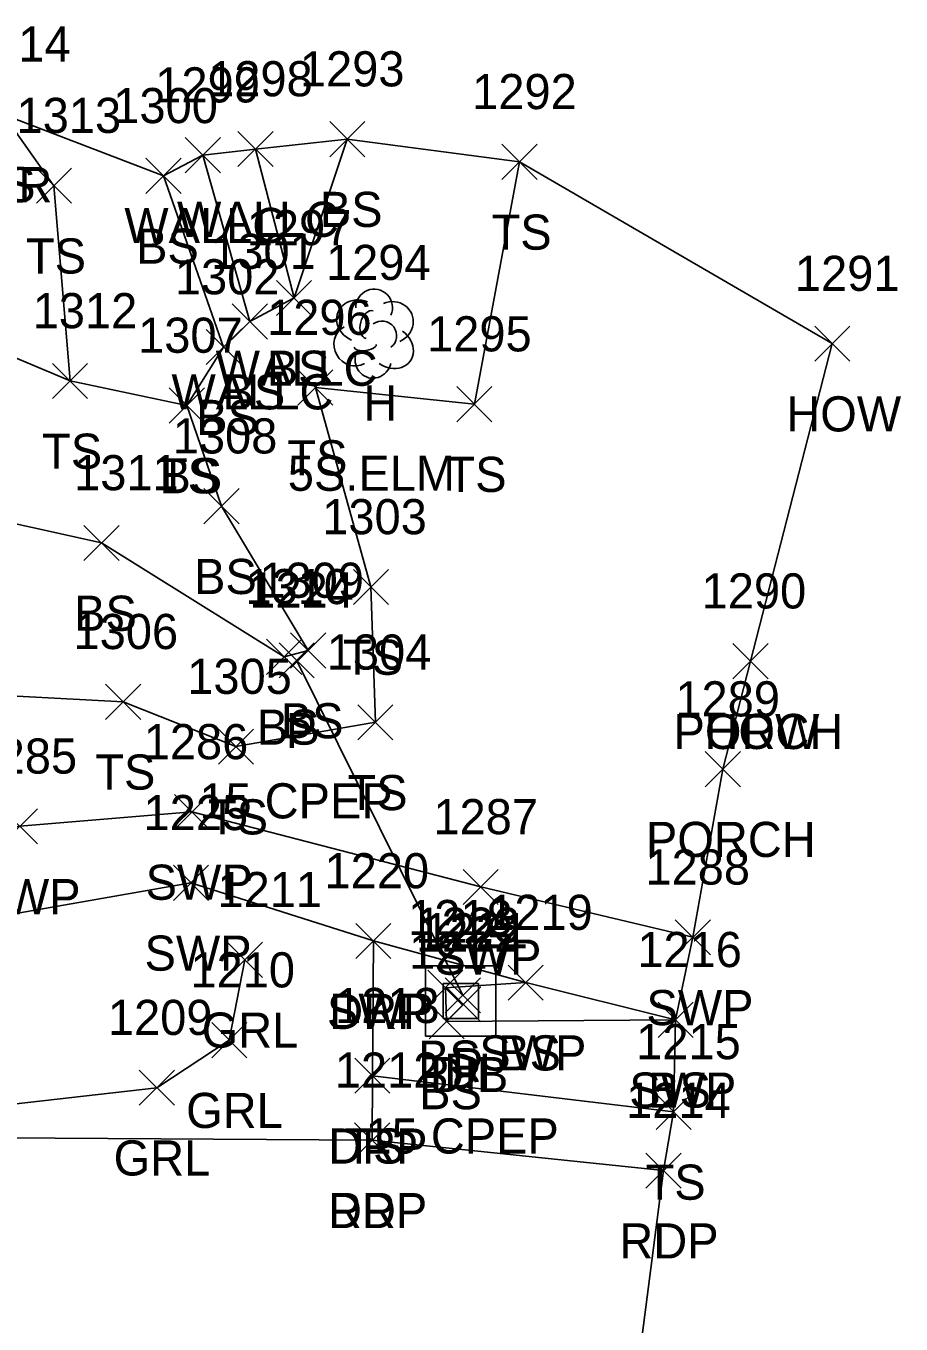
# Model space of a CAD drawing. Extents: x 1505684 to 1510253, y 730355 to 731397.
# Drawn here: x 1510203.3 to 1510253.1, y 730918.5 to 730992.4 of the extents above; entities that cross this region are included whole.
import ezdxf

# ---------------------------------------------------------------- set-up
doc = ezdxf.new("R2010")
doc.units = 0
for name, color, linetype in [('D_A', 7, 'Continuous'), ('D_C', 7, 'Continuous'), ('D_I', 7, 'Continuous'), ('D_TIC', 7, 'Continuous'), ('DCP', 7, 'Continuous'), ('DS', 7, 'Continuous'), ('L_A', 7, 'Continuous'), ('L_C', 7, 'Continuous'), ('L_I', 7, 'Continuous'), ('L_TIC', 7, 'Continuous'), ('LBC', 7, 'Continuous'), ('LBF', 7, 'Continuous'), ('LELB', 7, 'Continuous'), ('LSOGP', 7, 'Continuous'), ('LTD', 7, 'Continuous'), ('LW', 7, 'Continuous'), ('P_A', 7, 'Continuous'), ('P_I', 7, 'Continuous'), ('P_TIC', 7, 'Continuous'), ('PET', 7, 'Continuous'), ('R_A', 7, 'Continuous'), ('R_I', 7, 'Continuous'), ('R_TIC', 7, 'Continuous'), ('RDP', 7, 'Continuous'), ('RGR', 7, 'Continuous'), ('RSW', 7, 'Continuous')]:
    doc.layers.add(name, color=color, linetype=linetype)

msp = doc.modelspace()

# ---------------------------------------------------------------- linework, layer by layer
at = {"layer": 'D_TIC'}
for points in [[(1510217.701, 730955.254), (1510219.701, 730957.254)], [(1510219.701, 730955.254), (1510217.701, 730957.254)], [(1510227.154, 730936.18), (1510229.154, 730938.18)], [(1510229.154, 730936.18), (1510227.154, 730938.18)], [(1510227.185, 730935.675), (1510229.185, 730937.675)], [(1510229.185, 730935.675), (1510227.185, 730937.675)]]:
    msp.add_lwpolyline(points, dxfattribs=at)
at = {"layer": 'DCP'}
msp.add_lwpolyline([(1510228.154, 730937.18), (1510218.701, 730956.254)], dxfattribs=at)
at = {"layer": 'DS'}
for p, q in [((1510226.041, 730938.864), (1510230.041, 730938.864)), ((1510226.041, 730934.864), (1510226.041, 730938.864)), ((1510230.041, 730938.864), (1510230.041, 730934.864)), ((1510227.041, 730935.864), (1510227.041, 730937.864)), ((1510227.041, 730937.864), (1510229.041, 730937.864)), ((1510229.041, 730937.864), (1510229.041, 730935.864)), ((1510228.046, 730936.865), (1510228.046, 730936.865)), ((1510228.046, 730936.865), (1510228.046, 730936.865)), ((1510229.041, 730935.864), (1510227.041, 730935.864)), ((1510230.041, 730934.864), (1510226.041, 730934.864))]:
    msp.add_line(p, q, dxfattribs=at)
at = {"layer": 'L_TIC'}
for points in [[(1510220.581, 730984.917), (1510222.581, 730986.917)], [(1510222.581, 730984.917), (1510220.581, 730986.917)], [(1510212.36, 730984.003), (1510214.36, 730986.003)], [(1510214.36, 730984.003), (1510212.36, 730986.003)], [(1510215.358, 730984.353), (1510217.358, 730986.353)], [(1510217.358, 730984.353), (1510215.358, 730986.353)], [(1510230.383, 730983.623), (1510232.383, 730985.623)], [(1510232.383, 730983.623), (1510230.383, 730985.623)], [(1510203.891, 730982.266), (1510205.891, 730984.266)], [(1510205.891, 730982.266), (1510203.891, 730984.266)], [(1510210.127, 730982.825), (1510212.127, 730984.825)], [(1510212.127, 730982.825), (1510210.127, 730984.825)], [(1510217.556, 730975.876), (1510219.556, 730977.876)], [(1510219.556, 730975.876), (1510217.556, 730977.876)], [(1510217.556, 730975.876), (1510219.556, 730977.876)], [(1510219.556, 730975.876), (1510217.556, 730977.876)], [(1510215.042, 730974.532), (1510217.042, 730976.532)], [(1510217.042, 730974.532), (1510215.042, 730976.532)], [(1510215.042, 730974.532), (1510217.042, 730976.532)], [(1510217.042, 730974.532), (1510215.042, 730976.532)], [(1510213.547, 730973.081), (1510215.547, 730975.081)], [(1510215.547, 730973.081), (1510213.547, 730975.081)], [(1510213.547, 730973.081), (1510215.547, 730975.081)], [(1510215.547, 730973.081), (1510213.547, 730975.081)], [(1510248.179, 730973.278), (1510250.179, 730975.278)], [(1510250.179, 730973.278), (1510248.179, 730975.278)], [(1510204.808, 730971.154), (1510206.808, 730973.154)], [(1510206.808, 730971.154), (1510204.808, 730973.154)], [(1510204.808, 730971.154), (1510206.808, 730973.154)], [(1510206.808, 730971.154), (1510204.808, 730973.154)], [(1510218.767, 730970.776), (1510220.767, 730972.776)], [(1510220.767, 730970.776), (1510218.767, 730972.776)], [(1510211.454, 730969.755), (1510213.454, 730971.755)], [(1510213.454, 730969.755), (1510211.454, 730971.755)], [(1510211.454, 730969.755), (1510213.454, 730971.755)], [(1510213.454, 730969.755), (1510211.454, 730971.755)], [(1510227.817, 730969.834), (1510229.817, 730971.834)], [(1510229.817, 730969.834), (1510227.817, 730971.834)], [(1510213.424, 730964.024), (1510215.424, 730966.024)], [(1510215.424, 730964.024), (1510213.424, 730966.024)], [(1510206.598, 730961.932), (1510208.598, 730963.932)], [(1510208.598, 730961.932), (1510206.598, 730963.932)], [(1510221.93, 730959.428), (1510223.93, 730961.428)], [(1510223.93, 730959.428), (1510221.93, 730961.428)], [(1510218.359, 730955.811), (1510220.359, 730957.811)], [(1510220.359, 730955.811), (1510218.359, 730957.811)], [(1510216.995, 730955.45), (1510218.995, 730957.45)], [(1510218.995, 730955.45), (1510216.995, 730957.45)], [(1510243.525, 730955.202), (1510245.525, 730957.202)], [(1510245.525, 730955.202), (1510243.525, 730957.202)], [(1510243.525, 730955.202), (1510245.525, 730957.202)], [(1510245.525, 730955.202), (1510243.525, 730957.202)], [(1510207.834, 730952.892), (1510209.834, 730954.892)], [(1510209.834, 730952.892), (1510207.834, 730954.892)], [(1510207.834, 730952.892), (1510209.834, 730954.892)], [(1510209.834, 730952.892), (1510207.834, 730954.892)], [(1510222.184, 730951.724), (1510224.184, 730953.724)], [(1510224.184, 730951.724), (1510222.184, 730953.724)], [(1510214.25, 730950.342), (1510216.25, 730952.342)], [(1510216.25, 730950.342), (1510214.25, 730952.342)], [(1510241.954, 730949.059), (1510243.954, 730951.059)], [(1510243.954, 730949.059), (1510241.954, 730951.059)], [(1510226.166, 730936.613), (1510228.166, 730938.613)], [(1510228.166, 730936.613), (1510226.166, 730938.613)], [(1510230.735, 730936.908), (1510232.735, 730938.908)], [(1510232.735, 730936.908), (1510230.735, 730938.908)], [(1510226.233, 730934.7), (1510228.233, 730936.7)], [(1510228.233, 730934.7), (1510226.233, 730936.7)], [(1510239.267, 730934.792), (1510241.267, 730936.792)], [(1510241.267, 730934.792), (1510239.267, 730936.792)], [(1510222.012, 730931.607), (1510224.012, 730933.607)], [(1510224.012, 730931.607), (1510222.012, 730933.607)], [(1510239.149, 730929.551), (1510241.149, 730931.551)], [(1510241.149, 730929.551), (1510239.149, 730931.551)]]:
    msp.add_lwpolyline(points, dxfattribs=at)
at = {"layer": 'LBC'}
msp.add_lwpolyline([(1510244.525, 730956.202), (1510249.179, 730974.278)], dxfattribs=at)
at = {"layer": 'LBF'}
msp.add_lwpolyline([(1510242.954, 730950.059), (1510244.525, 730956.202)], dxfattribs=at)
at = {"layer": 'LELB'}
for points in [[(1510205.808, 730972.154), (1510204.891, 730983.266), (1510202.014, 730987.326)], [(1510221.581, 730985.917), (1510218.556, 730976.876), (1510216.042, 730975.532), (1510214.547, 730974.081)], [(1510231.383, 730984.623), (1510228.817, 730970.834), (1510219.767, 730971.776), (1510222.93, 730960.428), (1510223.184, 730952.724), (1510215.25, 730951.342), (1510208.834, 730953.892)], [(1510211.127, 730983.825), (1510214.547, 730974.081), (1510212.454, 730970.755), (1510214.424, 730965.024), (1510219.359, 730956.811), (1510217.995, 730956.45), (1510207.598, 730962.932), (1510199.546, 730964.713), (1510193.439, 730958.459), (1510194.352, 730951.448), (1510175.146, 730950.785), (1510171.38, 730951.139)], [(1510212.454, 730970.755), (1510205.808, 730972.154), (1510193.91, 730977.171)], [(1510197.45, 730950.656), (1510199.578, 730954.377), (1510208.834, 730953.892)], [(1510240.267, 730935.792), (1510227.233, 730935.7), (1510227.166, 730937.613), (1510231.735, 730937.908)], [(1510223.012, 730932.607), (1510240.149, 730930.551)]]:
    msp.add_lwpolyline(points, dxfattribs=at)
at = {"layer": 'LSOGP'}
msp.add_lwpolyline([(1510237.501, 730911.225), (1510239.574, 730927.207), (1510240.149, 730930.551), (1510240.267, 730935.792), (1510241.241, 730940.486), (1510242.954, 730950.059), (1510244.525, 730956.202), (1510249.179, 730974.278), (1510231.383, 730984.623), (1510221.581, 730985.917), (1510216.358, 730985.353), (1510213.36, 730985.003), (1510211.127, 730983.825), (1510202.014, 730987.326)], dxfattribs=at)
at = {"layer": 'LTD'}
msp.add_line((1510223.064, 730974.899), (1510223.064, 730974.899), dxfattribs=at)
msp.add_line((1510223.064, 730974.899), (1510223.064, 730974.899), dxfattribs=at)
msp.add_arc((1510223.111, 730976.333), 1.047, 335.52715, 180.95627, dxfattribs=at)
for centre, major_axis, ratio, start_param, end_param in [((1510222.272, 730975.566), (1.21, -0.512), 0.895232, 1.570796, 4.712389), ((1510222.856, 730975.358), (-0.208, -0.792), 0.645439, 3.141593, 6.283185), ((1510224.106, 730975.483), (-1.141, -0.483), 0.949671, 1.570796, 4.712389), ((1510223.564, 730974.733), (-0.5, 0.667), 0.989748, 3.141593, 6.283185), ((1510221.981, 730974.191), (0.584, -1.042), 0.959034, 3.141593, 6.283185), ((1510224.064, 730974.066), (-1.09, 0.792), 0.841452, 1.570796, 4.712389), ((1510222.606, 730974.149), (-0.625, -0.083), 0.423636, 0, 3.141593), ((1510223.064, 730973.399), (0.265, 1.061), 0.942809, 1.570796, 4.712389)]:
    msp.add_ellipse(centre, major_axis=major_axis, ratio=ratio, start_param=start_param, end_param=end_param, dxfattribs=at)
at = {"layer": 'LW'}
for points in [[(1510213.36, 730985.003), (1510216.042, 730975.532)], [(1510218.556, 730976.876), (1510216.358, 730985.353)]]:
    msp.add_lwpolyline(points, dxfattribs=at)
at = {"layer": 'P_TIC'}
for points in [[(1510221.998, 730927.933), (1510223.998, 730929.933)], [(1510223.998, 730927.933), (1510221.998, 730929.933)], [(1510238.574, 730926.207), (1510240.574, 730928.207)], [(1510240.574, 730926.207), (1510238.574, 730928.207)]]:
    msp.add_lwpolyline(points, dxfattribs=at)
at = {"layer": 'PET'}
msp.add_lwpolyline([(1510233.913, 730897.188), (1510219.776, 730900.306), (1510216.555, 730900.691), (1510208.471, 730901.46), (1510192.217, 730899.998), (1510191.338, 730913.015), (1510189.909, 730929.156), (1510222.998, 730928.933), (1510239.574, 730927.207)], dxfattribs=at)
at = {"layer": 'R_TIC'}
for points in [[(1510211.746, 730946.623), (1510213.746, 730948.623)], [(1510213.746, 730946.623), (1510211.746, 730948.623)], [(1510201.952, 730945.804), (1510203.952, 730947.804)], [(1510203.952, 730945.804), (1510201.952, 730947.804)], [(1510211.685, 730942.587), (1510213.685, 730944.587)], [(1510213.685, 730942.587), (1510211.685, 730944.587)], [(1510228.176, 730942.355), (1510230.176, 730944.355)], [(1510230.176, 730942.355), (1510228.176, 730944.355)], [(1510240.241, 730939.486), (1510242.241, 730941.486)], [(1510242.241, 730939.486), (1510240.241, 730941.486)], [(1510222.067, 730939.277), (1510224.067, 730941.277)], [(1510224.067, 730939.277), (1510222.067, 730941.277)], [(1510222.067, 730939.277), (1510224.067, 730941.277)], [(1510224.067, 730939.277), (1510222.067, 730941.277)], [(1510214.754, 730938.205), (1510216.754, 730940.205)], [(1510216.754, 730938.205), (1510214.754, 730940.205)], [(1510230.735, 730936.908), (1510232.735, 730938.908)], [(1510232.735, 730936.908), (1510230.735, 730938.908)], [(1510239.267, 730934.792), (1510241.267, 730936.792)], [(1510241.267, 730934.792), (1510239.267, 730936.792)], [(1510213.87, 730933.634), (1510215.87, 730935.634)], [(1510215.87, 730933.634), (1510213.87, 730935.634)], [(1510222.012, 730931.607), (1510224.012, 730933.607)], [(1510224.012, 730931.607), (1510222.012, 730933.607)], [(1510209.742, 730930.929), (1510211.742, 730932.929)], [(1510211.742, 730930.929), (1510209.742, 730932.929)], [(1510221.998, 730927.933), (1510223.998, 730929.933)], [(1510223.998, 730927.933), (1510221.998, 730929.933)]]:
    msp.add_lwpolyline(points, dxfattribs=at)
at = {"layer": 'RDP'}
msp.add_lwpolyline([(1510222.998, 730928.933), (1510223.012, 730932.607), (1510223.067, 730940.277)], dxfattribs=at)
at = {"layer": 'RGR'}
msp.add_lwpolyline([(1510190.209, 730929.584), (1510210.742, 730931.929), (1510214.87, 730934.634), (1510215.754, 730939.205)], dxfattribs=at)
at = {"layer": 'RSW'}
msp.add_lwpolyline([(1510240.267, 730935.792), (1510231.735, 730937.908), (1510223.067, 730940.277), (1510212.685, 730943.587), (1510187.037, 730939.098), (1510165.729, 730937.348), (1510166.329, 730942.107), (1510170.157, 730941.882), (1510188.417, 730943.719), (1510202.952, 730946.804), (1510212.746, 730947.623), (1510229.176, 730943.355), (1510241.241, 730940.486)], dxfattribs=at)

# ---------------------------------------------------------------- texts
at = {"layer": 'D_A'}
for s, p in [('P', (1510218.079, 730951.254)), ('P', (1510227.532, 730932.18)), ('DIB', (1510226.287, 730931.675)), ('DI', (1510227.102, 730931.865))]:
    msp.add_text(s, height=2, dxfattribs=at).set_placement(p)
at = {"layer": 'D_C'}
for p in [(1510213.165, 730947.254), (1510222.618, 730928.18)]:
    msp.add_text('15 CPEP', height=2, dxfattribs=at).set_placement(p)
at = {"layer": 'D_I'}
for s, p in [('1224', (1510216.008, 730959.254)), ('1223', (1510225.461, 730940.18)), ('1222', (1510225.492, 730939.675)), ('1221', (1510225.92, 730939.865))]:
    msp.add_text(s, height=2, dxfattribs=at).set_placement(p)
at = {"layer": 'L_A'}
for s, p in [('LER', (1510199.597, 730982.326)), ('TS', (1510200.424, 730982.326)), ('BS', (1510220.021, 730980.917)), ('WALLC', (1510211.893, 730980.353)), ('WALLC', (1510208.895, 730980.003)), ('TS', (1510229.793, 730979.623)), ('BS', (1510209.568, 730978.825)), ('TS', (1510203.301, 730978.266)), ('WALLC', (1510214.091, 730971.876)), ('BS', (1510216.997, 730971.876)), ('WALLC', (1510211.578, 730970.532)), ('BS', (1510214.483, 730970.532)), ('H', (1510222.497, 730969.899)), ('BS', (1510212.988, 730969.081)), ('BS', (1510212.988, 730969.081)), ('HOW', (1510246.564, 730969.278)), ('TS', (1510204.218, 730967.154)), ('TS', (1510204.218, 730967.154)), ('TS', (1510218.176, 730966.776)), ('TS', (1510210.864, 730965.755)), ('BS', (1510210.895, 730965.755)), ('TS', (1510227.227, 730965.834)), ('BS', (1510212.865, 730960.024)), ('BS', (1510206.039, 730957.932)), ('TS', (1510221.34, 730955.428)), ('BS', (1510216.436, 730951.45)), ('BS', (1510217.8, 730951.811)), ('PORCH', (1510240.147, 730951.202)), ('HOW', (1510241.911, 730951.202)), ('TS', (1510207.244, 730948.892)), ('TS', (1510207.244, 730948.892)), ('TS', (1510221.594, 730947.724)), ('TS', (1510213.659, 730946.342)), ('PORCH', (1510238.576, 730945.059)), ('BS', (1510230.176, 730932.908)), ('BS', (1510225.607, 730932.613)), ('BS', (1510225.674, 730930.7)), ('BS', (1510238.708, 730930.792)), ('TS', (1510221.422, 730927.607)), ('TS', (1510238.558, 730925.551))]:
    msp.add_text(s, height=2, dxfattribs=at).set_placement(p)
at = {"layer": 'L_C'}
msp.add_text('5S.ELM', height=2, dxfattribs=at).set_placement((1510218.198, 730965.899))
at = {"layer": 'L_I'}
for s, p in [('1314', (1510199.888, 730990.326)), ('1314', (1510199.888, 730990.326)), ('1293', (1510218.888, 730988.917)), ('1298', (1510213.665, 730988.353)), ('1299', (1510210.659, 730988.003)), ('1292', (1510228.69, 730987.623)), ('1300', (1510208.269, 730986.825)), ('1313', (1510202.765, 730986.266)), ('1297', (1510215.863, 730979.876)), ('1297', (1510215.863, 730979.876)), ('1301', (1510213.838, 730978.532)), ('1301', (1510213.838, 730978.532)), ('1294', (1510220.371, 730977.899)), ('1302', (1510211.776, 730977.081)), ('1302', (1510211.776, 730977.081)), ('1291', (1510247.053, 730977.278)), ('1312', (1510203.682, 730975.154)), ('1312', (1510203.682, 730975.154)), ('1296', (1510217.019, 730974.776)), ('1307', (1510209.683, 730973.755)), ('1307', (1510209.683, 730973.755)), ('1295', (1510226.124, 730973.834)), ('1308', (1510211.652, 730968.024)), ('1311', (1510206.039, 730965.932)), ('1303', (1510220.159, 730963.428)), ('1310', (1510215.783, 730959.45)), ('1309', (1510216.58, 730959.811)), ('1290', (1510241.746, 730959.202)), ('1290', (1510241.746, 730959.202)), ('1306', (1510206.007, 730956.892)), ('1306', (1510206.007, 730956.892)), ('1304', (1510220.413, 730955.724)), ('1305', (1510212.478, 730954.342)), ('1289', (1510240.253, 730953.059)), ('1219', (1510229.601, 730940.908)), ('1218', (1510225.04, 730940.613)), ('1217', (1510225.107, 730938.7)), ('1216', (1510238.086, 730938.792)), ('1213', (1510220.886, 730935.607)), ('1215', (1510238.023, 730933.551))]:
    msp.add_text(s, height=2, dxfattribs=at).set_placement(p)
at = {"layer": 'P_A'}
for p in [(1510220.486, 730923.933), (1510237.063, 730922.207)]:
    msp.add_text('RDP', height=2, dxfattribs=at).set_placement(p)
at = {"layer": 'P_I'}
for s, p in [('1212', (1510220.872, 730931.933)), ('1214', (1510237.448, 730930.207))]:
    msp.add_text(s, height=2, dxfattribs=at).set_placement(p)
at = {"layer": 'R_A'}
for s, p in [('SWP', (1510210.108, 730942.623)), ('SWP', (1510200.315, 730941.804)), ('SWP', (1510210.047, 730938.587)), ('SWP', (1510226.539, 730938.355)), ('SWP', (1510220.429, 730935.277)), ('DRP', (1510220.555, 730935.277)), ('SWP', (1510238.603, 730935.486)), ('GRL', (1510213.297, 730934.205)), ('SWP', (1510229.097, 730932.908)), ('SWP', (1510237.629, 730930.792)), ('GRL', (1510212.413, 730929.634)), ('DRP', (1510220.501, 730927.607)), ('GRL', (1510208.286, 730926.929)), ('DRP', (1510220.486, 730923.933))]:
    msp.add_text(s, height=2, dxfattribs=at).set_placement(p)
at = {"layer": 'R_I'}
for s, p in [('1286', (1510209.998, 730950.623)), ('1285', (1510200.259, 730949.804)), ('1225', (1510209.992, 730946.587)), ('1287', (1510226.483, 730946.355)), ('1220', (1510220.288, 730943.277)), ('1220', (1510220.288, 730943.277)), ('1288', (1510238.548, 730943.486)), ('1211', (1510214.195, 730942.205)), ('1219', (1510229.601, 730940.908)), ('1216', (1510238.086, 730938.792)), ('1210', (1510212.657, 730937.634)), ('1213', (1510220.886, 730935.607)), ('1209', (1510207.963, 730934.929)), ('1212', (1510220.872, 730931.933))]:
    msp.add_text(s, height=2, dxfattribs=at).set_placement(p)

doc.saveas('drawing.dxf')
